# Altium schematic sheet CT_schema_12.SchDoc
size 146 x 119 mm
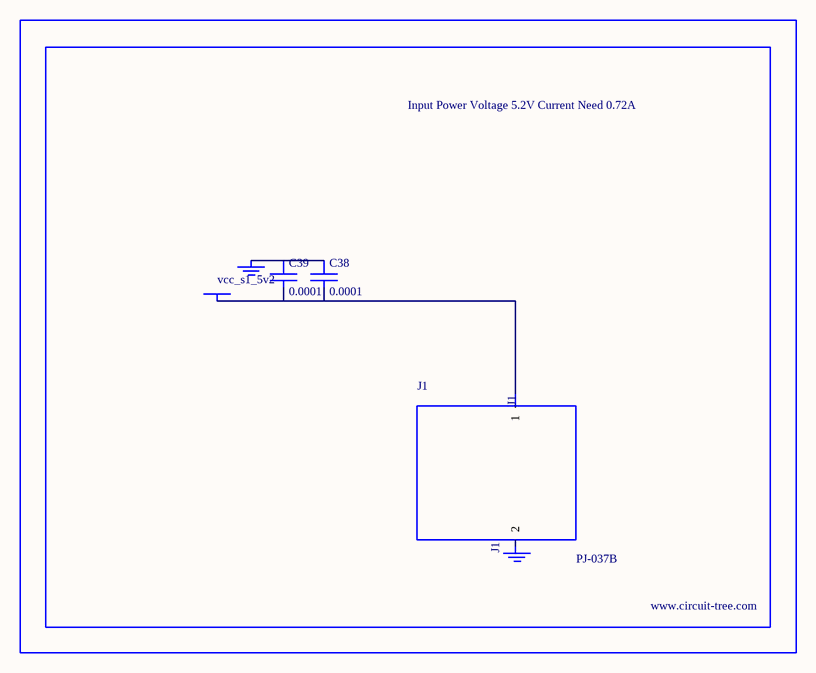
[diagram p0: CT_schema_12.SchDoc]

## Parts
BORDER11  (no value)
C38  0.0001  [EXV-9H]
C39  0.0001  [EXV-9H]
GND_INSTANCE_11_0  (no value)
GND_INSTANCE_11_1  (no value)
J1  PJ-037B  [PJ-037B_PACKAGE]
POWER_INSTANCE_11_0  vcc_s1_5v2

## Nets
NetC38_1: C38.1 C39.1 GND_INSTANCE_11_0.0(GND)
NetC38_2: C38.2 C39.2 J1.1 POWER_INSTANCE_11_0.0(PWR)

Not connected (* = marked no-connect by the designer): GND_INSTANCE_11_1 0(GND); J1 2

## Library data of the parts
BORDER11 = BORDER_PAGE11
C38 C39 = EDK107M035A9HAA
GND_INSTANCE_11_0 GND_INSTANCE_11_1 = GND
POWER_INSTANCE_11_0 = PWR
